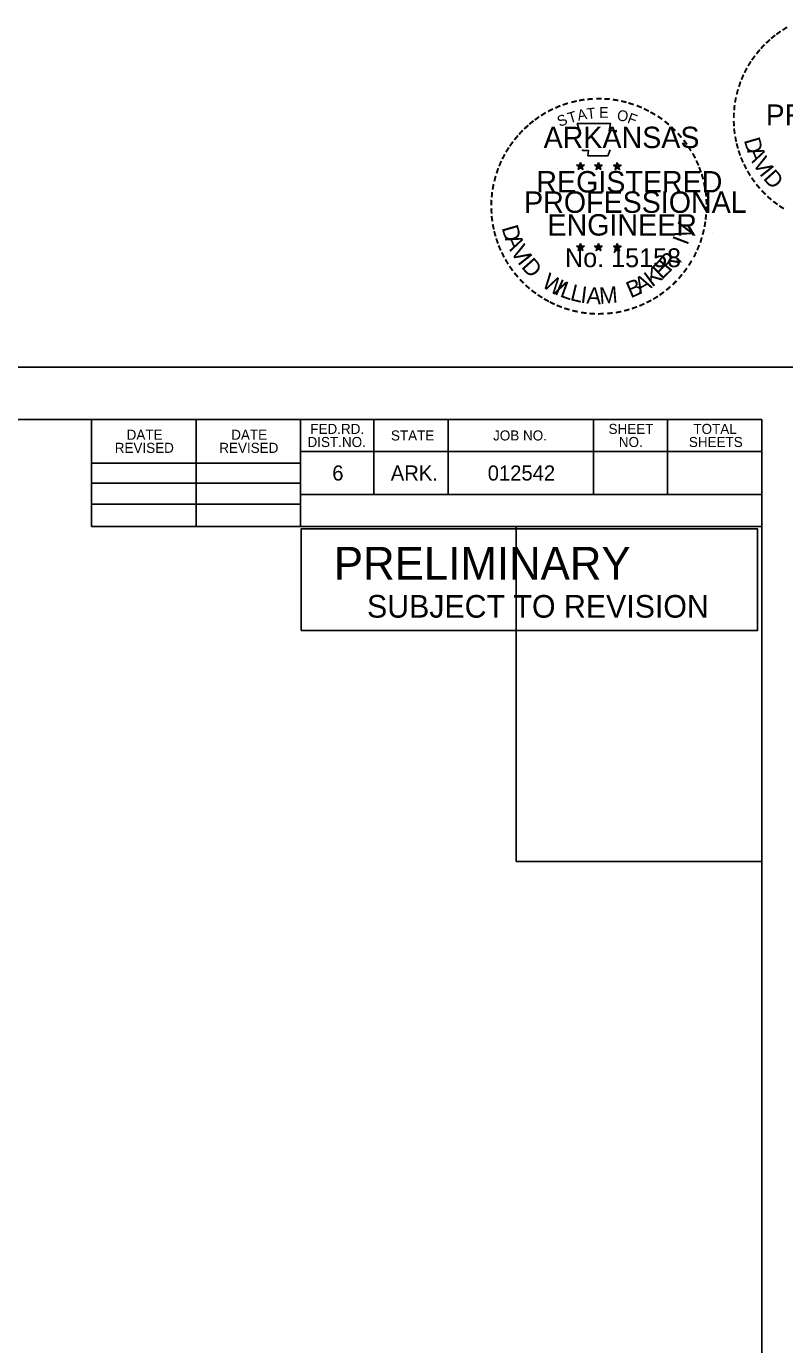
# Model space of a CAD drawing. Extents: x 32485 to 39285, y 55121 to 58033.
# Drawn here: x 37210 to 37571, y 57398 to 58026 of the extents above; entities that cross this region are included whole.
import ezdxf

# ---------------------------------------------------------------- set-up
doc = ezdxf.new("R2010")
doc.units = 0
for name, color, linetype in [('Default', 7, 'Continuous'), ('R_Border Notes', 7, 'Continuous'), ('R_Border PE', 7, 'Continuous'), ('R_Dimension', 7, 'Continuous'), ('SHET_Annotations', 7, 'Continuous'), ('SHET_Border-Lines', 7, 'Continuous'), ('SHET_Border-Text', 7, 'Continuous'), ('SHET_Stamp-PE-Chief-Eng', 7, 'Continuous'), ('SHET_Stamp-Seal', 7, 'Continuous')]:
    doc.layers.add(name, color=color, linetype=linetype)

msp = doc.modelspace()

# ---------------------------------------------------------------- linework, layer by layer
at = {"layer": 'Default'}
for points in [[(35885, 57863.91), (35885, 56763.91), (37585, 56763.91), (37585, 57863.91)], [(37340.49, 57738.35), (37557.9, 57738.35), (37557.9, 57786.89), (37340.49, 57786.89)]]:
    msp.add_lwpolyline(points, close=True, dxfattribs=at)
at = {"layer": 'R_Border Notes'}
for p, q in [((37240.54, 57787.97), (37240.54, 57838.91)), ((37290.37, 57787.97), (37290.37, 57838.91)), ((37340.19, 57838.91), (37340.19, 57787.97)), ((37375.08, 57838.91), (37375.08, 57803.13)), ((37410.47, 57838.91), (37410.47, 57803.13)), ((37479.73, 57838.91), (37479.73, 57803.13)), ((37515.12, 57838.91), (37515.12, 57803.13)), ((37560, 57823.75), (37340.19, 57823.75)), ((37560, 57823.85), (37560, 57823.85)), ((37240.54, 57818.18), (37340.19, 57818.18)), ((37240.54, 57808.59), (37340.19, 57808.59)), ((37240.54, 57798.59), (37340.19, 57798.59)), ((37560, 57803.13), (37340.19, 57803.13)), ((37355.29, 57803.13), (37560, 57803.13)), ((37560, 57787.97), (37240.54, 57787.97))]:
    msp.add_line(p, q, dxfattribs=at)
for points in [[(35885, 56763.91), (37585, 56763.91), (37585, 57863.91), (35885, 57863.91)], [(35910, 56788.91), (37560, 56788.91), (37560, 57838.91), (35910, 57838.91)], [(37240.54, 57787.97), (37560, 57787.97), (37560, 57838.91), (37240.54, 57838.91)]]:
    msp.add_lwpolyline(points, close=True, dxfattribs=at)
at = {"layer": 'R_Border PE'}
msp.add_lwpolyline([(37473.62, 57961.48), (37474.71, 57958.11), (37471.84, 57960.19), (37475.39, 57960.19), (37472.52, 57958.11), (37473.62, 57961.48)], dxfattribs=at)
at = {"layer": 'R_Dimension'}
for p, q in [((37471.84, 57960.19), (37473.62, 57959.62)), ((37471.84, 57960.19), (37473.13, 57959.96)), ((37471.84, 57960.19), (37473.05, 57959.56)), ((37472.52, 57958.11), (37473.62, 57959.62)), ((37472.52, 57958.11), (37473.16, 57959.35)), ((37472.52, 57958.11), (37473.61, 57959.21)), ((37473.62, 57961.48), (37473.41, 57960.2)), ((37474.71, 57958.11), (37473.61, 57959.2)), ((37473.62, 57959.62), (37473.62, 57961.48)), ((37473.62, 57961.48), (37473.87, 57960.21)), ((37475.39, 57960.19), (37473.62, 57959.62)), ((37474.71, 57958.11), (37473.62, 57959.62)), ((37475.39, 57960.19), (37473.93, 57959.94)), ((37474.71, 57958.11), (37474.01, 57959.59)), ((37475.39, 57960.19), (37474.35, 57959.67)), ((37480.36, 57960.19), (37482.14, 57959.62)), ((37480.36, 57960.19), (37481.65, 57959.96)), ((37480.36, 57960.19), (37481.57, 57959.56)), ((37481.04, 57958.11), (37482.14, 57959.62)), ((37481.04, 57958.11), (37481.68, 57959.35)), ((37481.04, 57958.11), (37482.13, 57959.21)), ((37482.14, 57961.48), (37481.93, 57960.2)), ((37483.22, 57958.11), (37482.13, 57959.2)), ((37482.14, 57959.62), (37482.14, 57961.48)), ((37482.14, 57961.48), (37482.39, 57960.21)), ((37483.91, 57960.19), (37482.14, 57959.62)), ((37483.22, 57958.11), (37482.14, 57959.62)), ((37483.91, 57960.19), (37482.45, 57959.94)), ((37483.22, 57958.11), (37482.52, 57959.59)), ((37483.91, 57960.19), (37482.87, 57959.67)), ((37489.35, 57960.13), (37491.13, 57959.56)), ((37489.35, 57960.13), (37490.64, 57959.9)), ((37489.35, 57960.13), (37490.56, 57959.5)), ((37490.03, 57958.04), (37491.13, 57959.56)), ((37490.03, 57958.04), (37490.67, 57959.29)), ((37490.03, 57958.04), (37491.12, 57959.15)), ((37491.13, 57961.42), (37490.92, 57960.14)), ((37492.22, 57958.04), (37491.12, 57959.14)), ((37491.13, 57959.56), (37491.13, 57961.42)), ((37491.13, 57961.42), (37491.38, 57960.15)), ((37492.9, 57960.13), (37491.13, 57959.56)), ((37492.22, 57958.04), (37491.13, 57959.56)), ((37492.9, 57960.13), (37491.44, 57959.88)), ((37492.22, 57958.04), (37491.52, 57959.53)), ((37492.9, 57960.13), (37491.86, 57959.61)), ((37471.82, 57921.57), (37473.6, 57921)), ((37471.82, 57921.57), (37473.11, 57921.34)), ((37471.82, 57921.57), (37473.03, 57920.94)), ((37472.5, 57919.48), (37473.6, 57921)), ((37472.5, 57919.48), (37473.14, 57920.73)), ((37472.5, 57919.48), (37473.59, 57920.59)), ((37473.6, 57922.86), (37473.39, 57921.58)), ((37474.69, 57919.48), (37473.59, 57920.58)), ((37473.6, 57921), (37473.6, 57922.86)), ((37473.6, 57922.86), (37473.85, 57921.59)), ((37475.37, 57921.57), (37473.6, 57921)), ((37474.69, 57919.48), (37473.6, 57921)), ((37475.37, 57921.57), (37473.91, 57921.32)), ((37474.69, 57919.48), (37473.99, 57920.97)), ((37475.37, 57921.57), (37474.33, 57921.05)), ((37480.33, 57921.57), (37482.11, 57921)), ((37480.33, 57921.57), (37481.62, 57921.34)), ((37480.33, 57921.57), (37481.54, 57920.94)), ((37481.01, 57919.48), (37482.11, 57921)), ((37481.01, 57919.48), (37481.65, 57920.73)), ((37481.01, 57919.48), (37482.1, 57920.59)), ((37482.11, 57922.86), (37481.9, 57921.58)), ((37483.2, 57919.48), (37482.1, 57920.58)), ((37482.11, 57921), (37482.11, 57922.86)), ((37482.11, 57922.86), (37482.36, 57921.59)), ((37483.88, 57921.57), (37482.11, 57921)), ((37483.2, 57919.48), (37482.11, 57921)), ((37483.88, 57921.57), (37482.42, 57921.32)), ((37483.2, 57919.48), (37482.5, 57920.97)), ((37483.88, 57921.57), (37482.84, 57921.05)), ((37489.34, 57921.51), (37491.12, 57920.95)), ((37489.34, 57921.51), (37490.63, 57921.28)), ((37489.34, 57921.51), (37490.55, 57920.89)), ((37490.02, 57919.43), (37491.12, 57920.95)), ((37490.02, 57919.43), (37490.66, 57920.68)), ((37490.02, 57919.43), (37491.11, 57920.54)), ((37491.12, 57922.81), (37490.91, 57921.52)), ((37492.21, 57919.43), (37491.11, 57920.52)), ((37491.12, 57920.95), (37491.12, 57922.81)), ((37491.12, 57922.81), (37491.37, 57921.53)), ((37492.89, 57921.51), (37491.12, 57920.95)), ((37492.21, 57919.43), (37491.12, 57920.95)), ((37492.89, 57921.51), (37491.43, 57921.26)), ((37492.21, 57919.43), (37491.51, 57920.92)), ((37492.89, 57921.51), (37491.85, 57920.99))]:
    msp.add_line(p, q, dxfattribs=at)
for points in [[(37472.05, 57979.96), (37473.42, 57975.75)], [(37489.95, 57975.26), (37490.68, 57976.71), (37487.19, 57976.59), (37487.94, 57979.96), (37472.05, 57979.96)], [(37474.56, 57967.61), (37474.56, 57967.16), (37477.43, 57967.07), (37477.15, 57964.65), (37486.69, 57964.65), (37487.72, 57967.39)], [(37482.14, 57961.48), (37483.22, 57958.11), (37480.36, 57960.19), (37483.91, 57960.19), (37481.04, 57958.11), (37482.14, 57961.48)], [(37491.13, 57961.42), (37492.22, 57958.04), (37489.35, 57960.13), (37492.9, 57960.13), (37490.03, 57958.04), (37491.13, 57961.42)], [(37473.6, 57922.86), (37474.69, 57919.48), (37471.82, 57921.57), (37475.37, 57921.57), (37472.5, 57919.48), (37473.6, 57922.86)], [(37482.11, 57922.86), (37483.2, 57919.48), (37480.33, 57921.57), (37483.88, 57921.57), (37481.01, 57919.48), (37482.11, 57922.86)], [(37491.12, 57922.81), (37492.21, 57919.43), (37489.34, 57921.51), (37492.89, 57921.51), (37490.02, 57919.43), (37491.12, 57922.81)]]:
    msp.add_lwpolyline(points, dxfattribs=at)
for centre, radius in [((37473.61, 57959.62), 0.878), ((37473.61, 57959.62), 0.737), ((37473.61, 57959.62), 0.59), ((37473.61, 57959.62), 0.505), ((37473.61, 57959.62), 0.381), ((37473.61, 57959.62), 0.253), ((37473.61, 57959.62), 0.151), ((37482.13, 57959.62), 0.878), ((37482.13, 57959.62), 0.737), ((37482.13, 57959.62), 0.59), ((37482.13, 57959.62), 0.505), ((37482.13, 57959.62), 0.381), ((37482.13, 57959.62), 0.253), ((37482.13, 57959.62), 0.151), ((37491.13, 57959.56), 0.878), ((37491.13, 57959.56), 0.737), ((37491.13, 57959.56), 0.59), ((37491.13, 57959.56), 0.505), ((37491.13, 57959.56), 0.381), ((37491.13, 57959.56), 0.253), ((37491.13, 57959.56), 0.151), ((37473.59, 57920.99), 0.878), ((37473.59, 57920.99), 0.737), ((37473.59, 57920.99), 0.59), ((37473.59, 57920.99), 0.505), ((37473.59, 57920.99), 0.381), ((37473.59, 57920.99), 0.253), ((37473.59, 57920.99), 0.151), ((37482.11, 57920.99), 0.878), ((37482.11, 57920.99), 0.737), ((37482.11, 57920.99), 0.59), ((37482.11, 57920.99), 0.505), ((37482.11, 57920.99), 0.381), ((37482.11, 57920.99), 0.253), ((37482.11, 57920.99), 0.151), ((37491.12, 57920.94), 0.878), ((37491.12, 57920.94), 0.737), ((37491.12, 57920.94), 0.59), ((37491.12, 57920.94), 0.505), ((37491.12, 57920.94), 0.381), ((37491.12, 57920.94), 0.253), ((37491.12, 57920.94), 0.151)]:
    msp.add_circle(centre, radius, dxfattribs=at)
at = {"layer": 'SHET_Border-Text'}
msp.add_lwpolyline([(37442.99, 57628.25), (37560, 57628.25), (37560, 57787.97), (37442.99, 57787.97)], close=True, dxfattribs=at)
at = {"layer": 'SHET_Stamp-PE-Chief-Eng'}
msp.add_line((37536.33, 57927.85), (37536.33, 57927.85), dxfattribs=at)
at = {"layer": 'SHET_Stamp-Seal'}
msp.add_lwpolyline([(37450.01, 57787.93), (37450.19, 57787.93), (37450.19, 57787.97), (37450.01, 57787.97)], close=True, dxfattribs=at)

# ---------------------------------------------------------------- texts
at = {"layer": 'Default'}
for s, height, p in [('PRELIMINARY', 15.6, (37356.06, 57762.62)), ('SUBJECT TO REVISION', 10.8, (37371.83, 57744.48))]:
    msp.add_text(s, height=height, dxfattribs=at).set_placement(p)
at = {"layer": 'R_Dimension'}
for s, height, rotation, p in [('-', 8, 36.23174, (37568.32, 58019.67)), ('-', 8, 34.06357, (37571.21, 58021.65)), ('-', 8, 42.96224, (37563.78, 58015.7)), ('-', 8, 38.95066, (37565.94, 58017.78)), ('-', 8, 54.23247, (37557.46, 58008.04)), ('-', 8, 50.61418, (37559.52, 58010.88)), ('-', 8, 48.42305, (37561.54, 58013.31)), ('-', 8, 62.87135, (37554.27, 58002.34)), ('-', 8, 58.07063, (37555.83, 58005.41)), ('-', 8, 72.39447, (37551.88, 57996.13)), ('-', 8, 67.77427, (37552.97, 57999.28)), ('-', 8, 75.46096, (37550.89, 57992.56)), ('-', 8.16, 28.79182, (37459.2, 57982.72)), ('-', 8.16, 24.30721, (37462.43, 57984.34)), ('-', 8.16, 19.17608, (37465.66, 57985.71)), ('-', 8.16, 13.63015, (37469.49, 57986.94)), ('A', 5.1, 11.21318, (37472.53, 57981.29)), ('-', 8.16, 10.21935, (37472.95, 57987.77)), ('T', 5.1, 6.02276, (37476.86, 57982.14)), ('-', 8.16, 5.89682, (37476.66, 57988.33)), ('-', 8.16, 0.18623, (37480.6, 57988.7)), ('E', 5.1, 0.83234, (37482.5, 57982.7)), ('-', 8.16, 357.74304, (37484.29, 57988.63)), ('-', 8.16, 352.16172, (37488.08, 57988.34)), ('-', 8.16, 347.20489, (37491.75, 57987.76)), ('-', 8.16, 342.3362, (37494.99, 57986.97)), ('-', 8.16, 337.85509, (37498.74, 57985.83)), ('-', 8.16, 334.12109, (37501.95, 57984.45)), ('-', 8, 85.18634, (37549.85, 57985.54)), ('-', 8, 81.20126, (37550.23, 57989)), ('-', 8.16, 38.95066, (37450.78, 57976.89)), ('-', 8.16, 36.23174, (37453.21, 57978.82)), ('-', 8.16, 34.06357, (37456.16, 57980.84)), ('S', 5.1, 21.59401, (37463.66, 57978.32)), ('T', 5.1, 16.4036, (37468.32, 57980.01)), ('O', 5.1, 350.4515, (37490.68, 57981.63)), ('F', 5.1, 340.07066, (37495.54, 57980.46)), ('-', 8.16, 329.64089, (37504.91, 57983.01)), ('-', 8.16, 325.86266, (37508.19, 57981.17)), ('-', 8.16, 320.52971, (37511.3, 57979)), ('-', 8, 94.19588, (37549.9, 57978.41)), ('-', 8, 89.06224, (37549.73, 57982.04)), ('-', 8.16, 50.61418, (37444.23, 57969.85)), ('-', 8.16, 48.42305, (37446.29, 57972.33)), ('-', 8.16, 42.96224, (37448.57, 57974.77)), ('-', 8.16, 315.57859, (37514.35, 57976.51)), ('-', 8.16, 309.87973, (37517.25, 57973.7)), ('-', 8, 98.94793, (37550.26, 57975.08)), ('-', 8.16, 58.07063, (37440.47, 57964.27)), ('-', 8.16, 54.23247, (37442.13, 57966.96)), ('-', 8.16, 306.65218, (37519.93, 57970.63)), ('-', 7.14, 303.67529, (37522.41, 57967.73)), ('-', 8, 101.71495, (37550.94, 57971.41)), ('-', 8, 105.45785, (37551.75, 57968.44)), ('D', 7.7, 286.28478, (37551.38, 57972.1)), ('-', 8.16, 67.77427, (37437.55, 57958.02)), ('-', 8.16, 62.87135, (37438.87, 57961.14)), ('-', 8.16, 299.66835, (37524.04, 57964.64)), ('-', 8.16, 294.66279, (37525.69, 57961.52)), ('-', 8, 109.08742, (37552.82, 57965.28)), ('-', 8, 114.06432, (37554.09, 57962.3)), ('A', 7.7, 292.78351, (37552.84, 57967.09)), ('V', 7.7, 300.79357, (37555.41, 57961.19)), ('-', 8.16, 72.39447, (37436.44, 57954.81)), ('-', 8.16, 290.57283, (37527, 57958.58)), ('-', 8.16, 285.12326, (37528.19, 57955.62)), ('-', 8, 115.72885, (37555.62, 57959.21)), ('-', 8, 120.44712, (37557.4, 57956.28)), ('I', 7.7, 308.35023, (37558.57, 57956.01)), ('D', 7.7, 311.97742, (37560.32, 57953.68)), ('-', 8.16, 81.20126, (37434.76, 57947.53)), ('-', 8.16, 75.46096, (37435.43, 57951.17)), ('-', 8.16, 280.54934, (37529.21, 57951.83)), ('-', 8, 125.89344, (37559.42, 57953.48)), ('-', 8, 130.71812, (37561.73, 57950.72)), ('-', 8.16, 89.06224, (37434.24, 57940.43)), ('-', 8.16, 85.18634, (37434.37, 57944.01)), ('-', 8.16, 276.59616, (37530.04, 57947.92)), ('-', 8.16, 274.33011, (37530.35, 57944.23)), ('-', 8, 134.22381, (37564.31, 57947.99)), ('-', 8, 138.93382, (37566.94, 57945.67)), ('-', 8, 144.64634, (37569.72, 57943.64)), ('-', 8.16, 94.19588, (37434.42, 57936.74)), ('-', 8.16, 263.5172, (37530.42, 57937.61)), ('-', 8.16, 269.94067, (37530.52, 57941.01)), ('-', 8, 148.08978, (37572.52, 57941.79)), ('-', 8.16, 98.94793, (37434.79, 57933.34)), ('-', 8.16, 101.71495, (37435.48, 57929.6)), ('D', 7.85, 286.28478, (37435.93, 57930.3)), ('V', 7.85, 72.65729, (37525.65, 57924.38)), ('-', 8.16, 260.99529, (37530.06, 57934.28)), ('-', 8.16, 105.45785, (37436.3, 57926.56)), ('-', 8.16, 109.08742, (37437.4, 57923.35)), ('A', 7.85, 292.78351, (37437.42, 57925.19)), ('I', 7.85, 69.03009, (37524.51, 57921.63)), ('-', 8.16, 252.86809, (37528.58, 57927.15)), ('-', 8.16, 255.7626, (37529.5, 57930.82)), ('-', 8.16, 114.06432, (37438.69, 57920.31)), ('-', 8.16, 115.72885, (37440.25, 57917.15)), ('V', 7.85, 300.79357, (37440.04, 57919.18)), ('I', 7.85, 308.35023, (37443.26, 57913.89)), ('R', 7.85, 50.36514, (37516.1, 57908.94)), ('-', 8.16, 244.61971, (37526.1, 57920.51)), ('-', 8.16, 247.88866, (37527.44, 57923.72)), ('-', 8.16, 120.44712, (37442.07, 57914.17)), ('-', 8.16, 125.89344, (37444.13, 57911.3)), ('D', 7.85, 311.97742, (37445.05, 57911.51)), ('K', 7.85, 36.91429, (37507.72, 57901.81)), ('E', 7.85, 44.01755, (37512.35, 57905.33)), (',', 7.85, 57.4684, (37519.78, 57913.44)), ('-', 8.16, 233.84524, (37522.04, 57913.34)), ('-', 8.16, 239.07125, (37524.09, 57916.67)), ('-', 8.16, 130.71812, (37446.48, 57908.49)), ('-', 8.16, 134.22381, (37449.12, 57905.71)), ('W', 7.85, 328.07311, (37454.63, 57902.51)), ('I', 7.85, 336.6877, (37460.68, 57898.89)), ('B', 7.85, 22.8589, (37497.45, 57896.66)), ('A', 7.85, 28.90423, (37502.02, 57898.57)), ('-', 8.16, 225.76533, (37517.41, 57907.58)), ('-', 8.16, 231.25377, (37519.85, 57910.46)), ('-', 8.16, 138.93382, (37451.8, 57903.34)), ('-', 8.16, 144.64634, (37454.63, 57901.27)), ('-', 8.16, 148.08978, (37457.49, 57899.38)), ('L', 7.85, 340.3149, (37463.38, 57897.65)), ('L', 7.85, 346.66249, (37468.28, 57895.89)), ('I', 7.85, 353.01009, (37473.34, 57894.68)), ('A', 7.85, 356.63729, (37476.28, 57894.25)), ('M', 7.85, 4.64735, (37482.83, 57893.95)), ('-', 8.16, 215.73633, (37511.94, 57902.58)), ('-', 8.16, 221.08509, (37514.74, 57904.99)), ('-', 8.16, 151.57039, (37460.45, 57897.72)), ('-', 8.16, 154.60019, (37463.11, 57896.46)), ('-', 8.16, 158.56121, (37466.29, 57895.17)), ('-', 8.16, 162.79826, (37469.79, 57894.08)), ('-', 8.16, 199.46435, (37499.97, 57895.8)), ('-', 8.16, 204.25161, (37503.19, 57897.21)), ('-', 8.16, 207.35684, (37506.38, 57898.84)), ('-', 8.16, 212.24909, (37509.22, 57900.6)), ('-', 8.16, 167.55551, (37473.44, 57893.25)), ('-', 8.16, 173.11546, (37477.38, 57892.68)), ('-', 8.16, 176.51827, (37481.19, 57892.41)), ('-', 8.16, 181.59176, (37484.99, 57892.51)), ('-', 8.16, 185.81666, (37489.11, 57892.9)), ('-', 8.16, 191.28576, (37492.87, 57893.57)), ('-', 8.16, 195.47429, (37496.58, 57894.59))]:
    msp.add_text(s, height=height, rotation=rotation, dxfattribs=at).set_placement(p)
for s, height, p in [('PROFESSIONAL', 10, (37561.93, 57979.09)), ('ARKANSAS', 10.2, (37456, 57968.3)), ('REGISTERED', 10.2, (37452.54, 57947.14)), ('PROFESSIONAL', 10.1998, (37446.69, 57937.43)), ('ENGINEER', 10.2, (37457.84, 57926.59)), ('No. 15158', 8.961, (37466.21, 57911.54)), ('AAMU', 0.000102, (37481.77, 57893.92))]:
    msp.add_text(s, height=height, dxfattribs=at).set_placement(p)
at = {"layer": 'SHET_Annotations'}
for s, p in [('FED.RD.', (37344.81, 57832.05)), ('SHEET', (37486.95, 57832.05)), ('TOTAL', (37527.37, 57832.05)), ('DATE', (37257.3, 57829.27)), ('DATE', (37307.12, 57829.27)), ('DIST.NO.', (37343.5, 57825.81)), ('STATE', (37383.25, 57828.93)), ('JOB NO.', (37431.92, 57828.93)), ('NO.', (37491.84, 57825.81)), ('SHEETS', (37525.22, 57825.81)), ('REVISED', (37251.62, 57823.03)), ('REVISED', (37301.44, 57823.03))]:
    msp.add_text(s, height=4.8, dxfattribs=at).set_placement(p)
at = {"layer": 'SHET_Border-Lines'}
for s, p in [('6', (37355.29, 57809.84)), ('ARK.', (37383.17, 57809.84)), ('012542', (37429.37, 57809.84))]:
    msp.add_text(s, height=7.2, dxfattribs=at).set_placement(p)
at = {"layer": 'SHET_Stamp-Seal'}
for s, height, p in [('PRELIMINARY', 0.013, (37450.02, 57787.95)), ('SUBJECT TO REVISION', 0.009, (37450.03, 57787.93))]:
    msp.add_text(s, height=height, dxfattribs=at).set_placement(p)

doc.saveas('drawing.dxf')
